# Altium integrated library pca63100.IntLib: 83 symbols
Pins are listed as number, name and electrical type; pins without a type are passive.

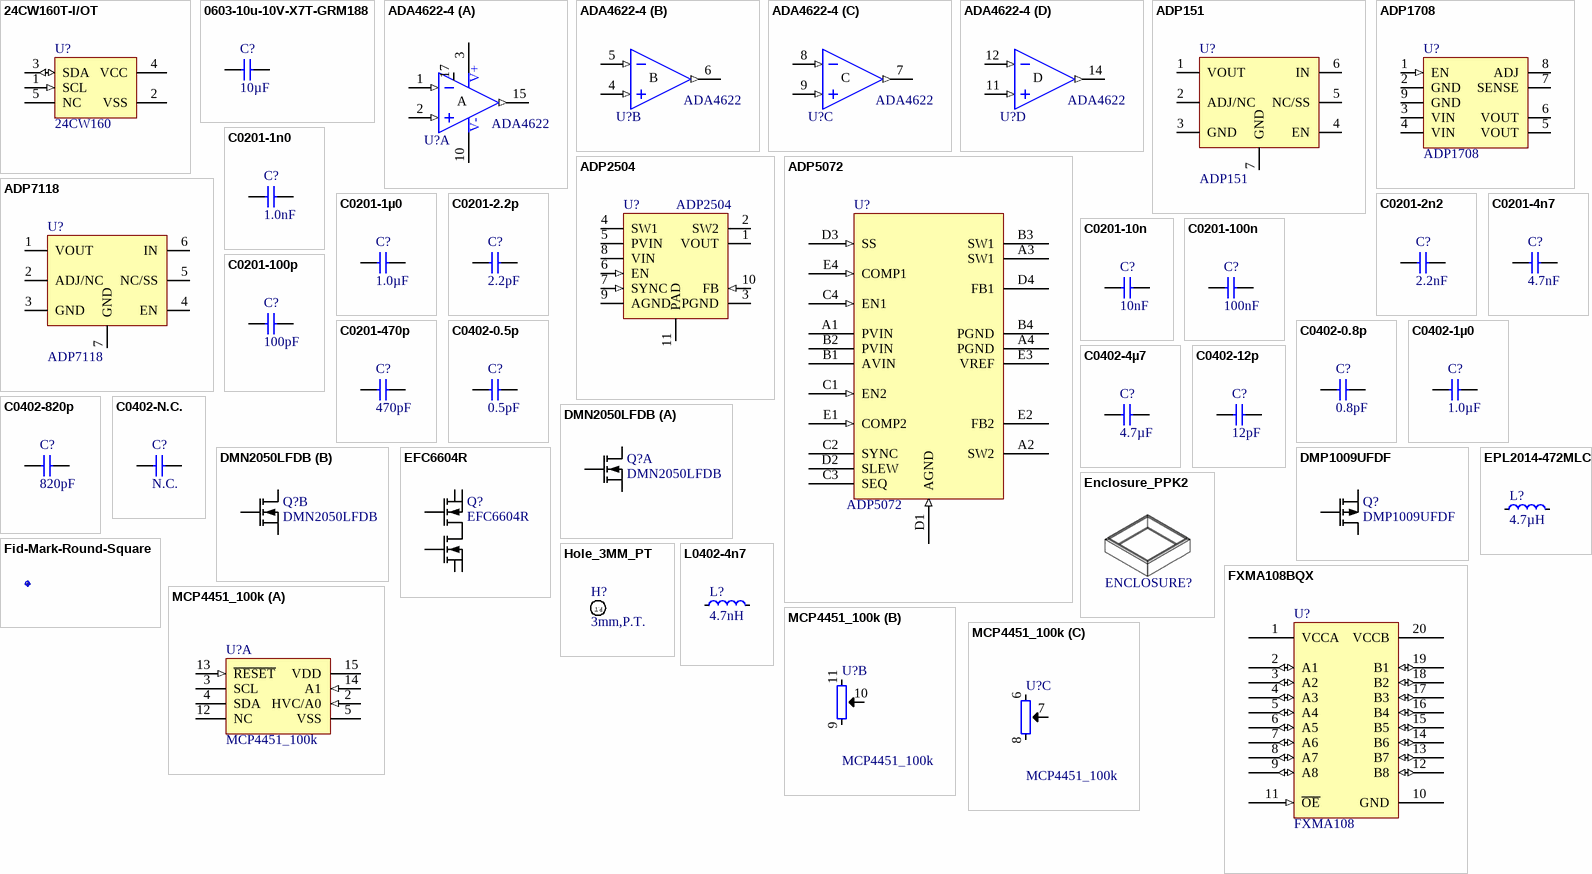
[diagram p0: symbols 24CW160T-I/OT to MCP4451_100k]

## 24CW160T-I/OT
designator U?, comment 24CW160
16 Kbit I2C Serial EEPROM with Software Write Protection, 1.6-5.5 V Supply; Part Number: 24CW160T-I/OT; Manufacturer: Microchip; Part number IPS: 00000004049; Artikkelnr Noca: N.A.; Pad Count: 5
footprint SOT-23-5
pins: 1 SCL (in), 2 VSS (power), 3 SDA (io), 4 VCC (power), 5 NC

## 0603-10u-10V-X7T-GRM188
designator C?, comment 10µF
CAP CER 10UF 10V X7T 0603; Part Number: 0603-10u-10V-X7T-GRM188; Manufacturer: Murata; Manufacturer Part Number: GRM188D71A106MA73; Part number IPS: 00000004696; Note: 10VDC; Artikkelnr Noca: N.A; Pad Count: 2
footprint CAPC1608X06L
pins: 1, 2

## ADA4622-4
designator U?, comment ADA4622
J-FET Amplifier 4 Circuit Rail-to-Rail 16-LFCSP (4x4); Part Number: ADA4622-4; Manufacturer: Analog Devices; Manufacturer Part Number: ADA4622-4ACPZ-RL; Part number IPS: 00000004963; Artikkelnr Noca: N.A.; Pad Count: 17
footprint QFN65P400X400X80_HS-17N
part A pins: 1 IN A- (in), 2 IN A+ (in), 3 VDD (power), 10 VSS (power), 13 NIC hidden, 15 OUTA (out), 16 NIC hidden, 17 EPAD (power) "Connect to VDD"
part B pins: 4 IN B+ (in), 5 IN B- (in), 6 OUTB (out)
part C pins: 7 OUTC (out), 8 IN C- (in), 9 IN C+ (in)
part D pins: 11 IN D+ (in), 12 IN D- (in), 14 OUTD (out)

## ADP151
designator U?
Ultralow Noise, 200 mA,CMOS Linear Regulator; Manufacturer: Analog Devices; Manufacturer Part Number: ADP151ACPZ-3.3-R7; Part number IPS: 00000004803; Artikkelnr Noca: N.A.; Pad Count: 7
footprint SON65P200X60_HS-7N
pins: 1 VOUT (power), 2 ADJ/NC, 3 GND, 4 EN, 5 NC/SS, 6 IN (power), 7 GND (power)

## ADP1708
designator U?
LDO, Adjustable, 1 Output 1A, 8-LFCSP-WD (3x3); Manufacturer: Analog Devices; Manufacturer Part Number: ADP1708ACPZ-R7; Part number IPS: 00000004966; Artikkelnr Noca: N.A.; Pad Count: 9
footprint SON50P300X80_HS-9N
pins: 1 EN (in), 2 GND (power), 3 VIN (power), 4 VIN (power), 5 VOUT (power), 6 VOUT (power), 7 SENSE, 8 ADJ, 9 GND (power)

## ADP2504
designator U?
Buck-Boost Switching Regulator IC Positive Adjustable 2.8V 1 Output 1A; Manufacturer: Analog Devices; Manufacturer Part Number: ADP2504ACPZ-R7; Part number IPS: 00000004965; Artikkelnr Noca: N.A.; Pad Count: 10
footprint SON50P300X80-HS-11N
pins: 1 VOUT (power), 2 SW2 (power), 3 PGND (power), 4 SW1 (power), 5 PVIN (power), 6 EN (in), 7 SYNC (in), 8 VIN (power), 9 AGND (power), 10 FB (in), 11 PAD (power)

## ADP5072
designator U?
Boost Switching Regulator IC Positive and Negative (Dual Rail) Adjustable 0.8V 2 Output 600mA, 1A 20-UFBGA,; Manufacturer: Analog Devices; Manufacturer Part Number: ADP5072ACBZ-R7; Part number IPS: 00000004804; Artikkelnr Noca: N.A.; Pad Count: 20
footprint BGA20C40P4X5_161X218X56
pins: A1 PVIN (power), A2 SW2 (power), A3 SW1 (power), A4 PGND (power), B1 AVIN (power), B2 PVIN (power), B3 SW1 (power), B4 PGND (power), C1 EN2 (in), C2 SYNC, C3 SEQ, C4 EN1 (in), D1 AGND (in), D2 SLEW, D3 SS (in), D4 FB1 (power), E1 COMP2 (in), E2 FB2 (power), E3 VREF (power), E4 COMP1 (in)

## ADP7118
designator U?
20 V, 200 mA, Low Noise,CMOS LDO Linear Regulator; Manufacturer: Analog Devices; Manufacturer Part Number: ADP7118ACPZN-R7; Part number IPS: 00000004964; Artikkelnr Noca: N.A.; Pad Count: 7
footprint SON65P200X60_HS-7N
pins: 1 VOUT (power), 2 ADJ/NC, 3 GND, 4 EN, 5 NC/SS, 6 IN (power), 7 GND (power)

## C0201-1n0
designator C?, comment 1.0nF
Capacitor, X7R, ±10%; Part Number: C0201-1n0; Part number IPS: 00000003206; Note: 16V; Artikkelnr Noca: N.A.; Pad Count: 2
footprint CAPC0603X03L_C
pins: 1, 2

## C0201-1µ0
designator C?, comment 1.0µF
Capacitor, X5R, ±10%; Part Number: C0201-1µ0; Part number IPS: 00000001723; Note: 10V; Artikkelnr Noca: N.A.; Pad Count: 2
footprint CAPC0603X03L_C
pins: 1, 2

## C0201-2.2p
designator C?, comment 2.2pF
Chip Cap 0201; Part Number: C0201-2.2p; Note: Chip Cap 1%; Artikkelnr Noca: N.A.; Pad Count: 2
footprint CAPC0603X03L_C
pins: 1, 2

## C0201-2n2
designator C?, comment 2.2nF
Capacitor, X7R, ±10%, 10V; Part Number: C0201-2n2; Part number IPS: 00000001778; Artikkelnr Noca: N.A.; Pad Count: 2
footprint CAPC0603X03L_C
pins: 1, 2

## C0201-4n7
designator C?, comment 4.7nF
Chip Cap 0201; Part Number: C0201-4n7; Part number IPS: 00000001243; Note: Chip Cap 1%; Artikkelnr Noca: N.A.; Pad Count: 2
footprint CAPC0603X03L_C
pins: 1, 2

## C0201-10n
designator C?, comment 10nF
Capacitor, X7R, ±10%; Part Number: C0201-10n; Part number IPS: 00000003480; Note: 10V; Artikkelnr Noca: N.A.; Pad Count: 2
footprint CAPC0603X03L_C
pins: 1, 2

## C0201-100n
designator C?, comment 100nF
Capacitor, X5R, ±10%; Part Number: C0201-100n; Part number IPS: 00000001248, 00000002505; Note: 16V; Artikkelnr Noca: N.A.; Pad Count: 2
footprint CAPC0603X03L_C
pins: 1, 2

## C0201-100p
designator C?, comment 100pF
Capacitor, NP0, ±2%, 25V; Part Number: C0201-100p; Manufacturer: Murata; Manufacturer Part Number: GRM0335C1E101GA01; Part number IPS: 00000007853; Artikkelnr Noca: N.A.; Pad Count: 2
footprint CAPC0603X03L_C
pins: 1, 2

## C0201-470p
designator C?, comment 470pF
Chip Cap 0201; Part Number: C0201-470p; Part number IPS: 00000005775; Note: Chip Cap 1%; Artikkelnr Noca: N.A.; Pad Count: 2
footprint CAPC0603X03L_C
pins: 1, 2

## C0402-0.5p
designator C?, comment 0.5pF
Capacitor, NP0, ±0.05pF; Part Number: C0402-0.5p; Manufacturer: Murata; Manufacturer Part Number: GJM1555C1HR50WB01; Part number IPS: 00000004293; Note: 50V; Artikkelnr Noca: 20020007; Pad Count: 2
footprint CAPC1005X04L
pins: 1, 2

## C0402-0.8p
designator C?, comment 0.8pF
Capacitor, NP0, ±5%; Part Number: C0402-0.8p; Manufacturer: Murata; Manufacturer Part Number: GRM1555C1HR80WA01D; Part number IPS: 00000007782; Note: 50V; Artikkelnr Noca: 20029147; Pad Count: 2
footprint CAPC1005X04L
pins: 1, 2

## C0402-1µ0
designator C?, comment 1.0µF
Capacitor, X5R, ±5%, 6.3V; Part Number: C0402-1µ0; Part number IPS: 00000007786, 00000003457; Artikkelnr Noca: 20039235; Pad Count: 2
footprint CAPC1005X04L
pins: 1, 2

## C0402-4µ7
designator C?, comment 4.7µF
Capacitor, X5R, ±20%; Part Number: C0402-4µ7; Part number IPS: 00000001251, 00000007165; Note: 10V; Artikkelnr Noca: 20039482; Pad Count: 2
footprint CAPC1005X04L
pins: 1, 2

## C0402-12p
designator C?, comment 12pF
Capacitor, NP0, ±2%; Part Number: C0402-12p; Part number IPS: 00000002398; Note: 50V; Artikkelnr Noca: 20029159; Pad Count: 2
footprint CAPC1005X04L
pins: 1, 2

## C0402-820p
designator C?, comment 820pF
Capacitor, NP0, ±5%; Part Number: C0402-820p; Part number IPS: 00000004365; Note: 50V; Artikkelnr Noca: 20029219; Pad Count: 2
footprint CAPC1005X04L
pins: 1, 2

## C0402-N.C.
designator C?, comment N.C.
Not mounted; Part Number: C0402-N.C.; Note: Chip Cap; Artikkelnr Noca: N.A.; Assembly: Not mounted; Pad Count: 2
footprint CAPC1005X04L_NC
pins: 1, 2

## DMN2050LFDB
designator Q?
Dual N Ch MOFET, 3.3A, 45mOhm @ 5A, 4.5V, 730mW; Manufacturer: Diodes Incorporated; Manufacturer Part Number: DMN2050LFDB-7; Part number IPS: 00000004782; Artikkelnr Noca: N.A.; Pad Count: 6
footprint DFN65P200X60_HS-6N
part A pins: 1 S1, 2 G1, 6 D1
part B pins: 3 D2, 4 S2, 5 G2

## DMP1009UFDF
designator Q?
P Ch MOFET, 11A, 30mOhm max, 2W; Manufacturer: Diodes Incorporated; Part number IPS: 00000004784; Artikkelnr Noca: N.A.; Pad Count: 6
footprint UDFN65P200X200X60_HS-6N
pins: 1 G, 2 S, 3 D

## EFC6604R
designator Q?
Dual MOSFET, Dual N Channel, 13 A, 12 V, 0.009 ohm, 4.5 V, 2.5 V; Manufacturer: ON Semiconductor; Manufacturer Part Number: EFC6604R-TR; Part number IPS: 00000004783; Artikkelnr Noca: N.A.; Pad Count: 6
footprint BGA6C65P2X3_146X191X22
pins: 1 S1, 2 G1, 3 S2, 4 S2, 5 G2, 6 S2

## Enclosure_PPK2
designator ENCLOSURE?, comment Plastic Enclosure  (value not drawn)
PPK2 Moulded plastic casing; Part Number: Enclosure_PPK2; Manufacturer: Proto Labs, Inc.; Manufacturer Part Number: PPK plexi rev 1.2; Part number IPS: 4971; Pad Count: 0
footprint Enclosure_PPK2

## EPL2014-472MLC
designator L?, comment 4.7µH
Shielded Power Inductor EPL2014 Low DCR Ind 4.7 uH 20 % 650mA; Part Number: EPL2014-472MLC; Manufacturer: Coilcraft; Part number IPS: 00000004697; Artikkelnr Noca: N.A.; Pad Count: 2
footprint IND_EPL2014
pins: 1, 2

## Fid-Mark-Round-Square
designator Fid?, comment Fiducial mark  (value not drawn)  (no BOM)
Part Number: Fid-Mark-Round-Square; Artikkelnr Noca: N.A.; Pad Count: 1
footprint Fiducial_Round-Square

## FXMA108BQX
designator U?, comment FXMA108
8-bit bidirectional voltage-level translator with auto-direction sensing; Part Number: FXMA108BQX; Manufacturer: Fairchild Semiconductor; Part number IPS: 00000004806; Note: Translator, Bidirectional; Artikkelnr Noca: N.A.; Pad Count: 20
footprint QFN50P450X250X80_HS-21N
pins: 1 VCCA (power), 2 A1 (io), 3 A2 (io), 4 A3 (io), 5 A4 (io), 6 A5 (io), 7 A6 (io), 8 A7 (io), 9 A8 (io), 10 GND (power), 11 ~{OE} (in), 12 B8 (io), 13 B7 (io), 14 B6 (io), 15 B5 (io), 16 B4 (io), 17 B3 (io), 18 B2 (io), 19 B1 (io), 20 VCCB (power)

## Hole_3MM_PT
designator H?, comment 3mm,P.T.  (no BOM)
Regular Plate Through, 3mm hole; Part Number: Hole_3MM_PT; Manufacturer: Nordic Semiconductor; Artikkelnr Noca: N.A.; Pad Count: 1
footprint HOLE_PT_3MM
pins: 1

## L0402-4n7
designator L?, comment 4.7nH
Inductor, 160mA, ±0.1nH; Part Number: L0402-4n7; Manufacturer: Murata; Manufacturer Part Number: LQP15MN4N7B02D; Part number IPS: 00000004366; Note: High frequency chip inductor ±5%; Artikkelnr Noca: 33029164; Pad Count: 2
footprint INDC1005X04L
pins: 1, 2

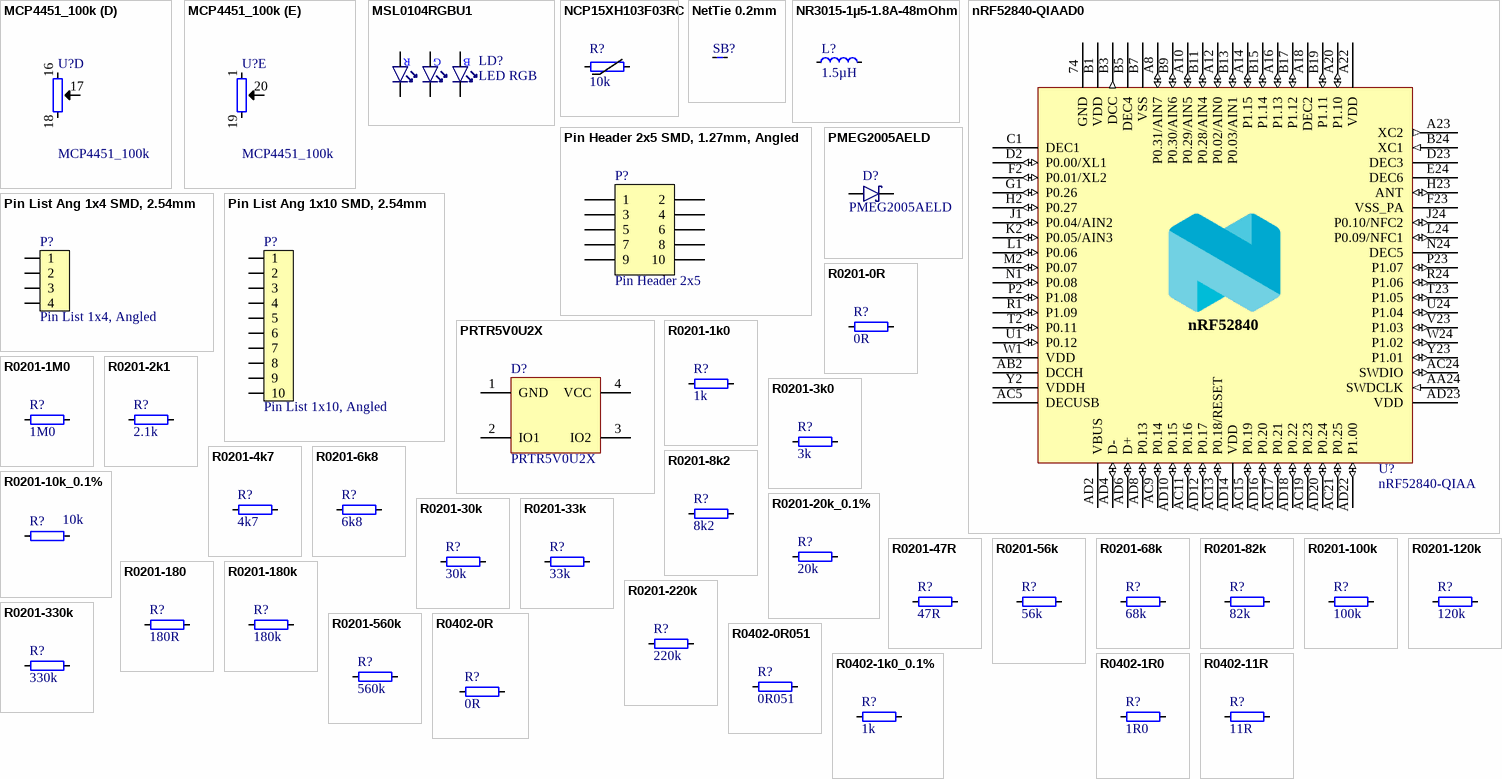
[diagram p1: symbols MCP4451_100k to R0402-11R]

## MCP4451_100k
designator U?
Quad Digital Potentiometer, 100k, 257 taps, I2C interface, Volatile Memory, 1.8-5.5V; Manufacturer: Microchip Technology; Manufacturer Part Number: MCP4451-104E/ML; Part number IPS: 00000004805; Artikkelnr Noca: 15070064; Pad Count: 20
footprint QFN50P400X400X80_HS-21N
part A pins: 2 HVC/A0 (in), 3 SCL, 4 SDA, 5 VSS (power), 12 NC, 13 ~{RESET} (in), 14 A1 (in), 15 VDD (power) "VDD 1.65V - 5.5V", 21 VSS (power) hidden to GND
part B pins: 9 P0A, 10 P0W (power), 11 P0B
part C pins: 6 P1B, 7 P1W (power), 8 P1A
part D pins: 16 P2B, 17 P2W (power), 18 P2A
part E pins: 1 P3B, 19 P3A, 20 P3W (power)

## MSL0104RGBU1
designator LD?, comment LED RGB
High brightness, side view RGB LED; Part Number: MSL0104RGBU1; Manufacturer: ROHM; Part number IPS: 00000007799; Artikkelnr Noca: N.A.; Pad Count: 7
footprint MSL0104
pins: 1 A_RED, 2 A_GREEN, 3 C_GREEN, 4 C_RED, 5 C_BLUE, 6 A_BLUE

## NCP15XH103F03RC
designator R?, comment 10k
THERMISTOR 10K OHM NTC 0402 SMD; Part Number: NCP15XH103F03RC; Manufacturer: Murata; Part number IPS: 00000007808; Note: Chip Res 1%; Artikkelnr Noca: N.A.; Pad Count: 2
footprint RESC1005X04L
pins: 1, 2

## NetTie 0.2mm
designator SB?, comment NetTie_200um  (value not drawn)  (net tie, no BOM)
Net Tie; Part Number: NetTie 0.2mm; Artikkelnr Noca: N.A.; Pad Count: 2
footprint NetTie_200um
pins: 1, 2

## NR3015-1µ5-1.8A-48mOhm
designator L?, comment 1.5µH
Ferrite Inductor, Shielded, 1,8A, 48mOhm; Part Number: NR3015-1µ5-1.8A-48mOhm; Manufacturer: Taiyo Yuden; Manufacturer Part Number: NR3015T1R5N; Part number IPS: 00000004698; Artikkelnr Noca: N.A.; Pad Count: 2
footprint TY-NR3015
pins: 1, 2

## nRF52840-QIAAD0
designator U?, comment nRF52840-QIAA
Multi-protocol Bluetooth Low Energy, IEEE 802.15.4, ANT and 2.4GHz proprietary system-on-chip; Part Number: nRF52840-QIAAD0; Manufacturer: Nordic Semiconductor; Part number IPS: 80000001648; Artikkelnr Noca: N.A.; Pad Count: 73
footprint AQFN50P700X700X85_HS-74N
pins: 74 GND (power), A8 P0.31/AIN7 (io), A10 P0.29/AIN5 (io), A12 P0.02/AIN0 (io), A14 P1.15 (io), A16 P1.13 (io), A18 DEC2 (power), A20 P1.10 (io), A22 VDD (power), A23 XC2 (out), AA24 SWDCLK (in), AB2 DCCH (power), AC5 DECUSB (power), AC9 P0.14 (io), AC11 P0.16 (io), AC13 P0.18/RESET (io), AC15 P0.19 (io), AC17 P0.21 (io), AC19 P0.23 (io), AC21 P0.25 (io), AC24 SWDIO (io), AD2 VBUS (power), AD4 D- (io), AD6 D+ (io), AD8 P0.13 (io), AD10 P0.15 (io), AD12 P0.17 (io), AD14 VDD (power), AD16 P0.20 (io), AD18 P0.22 (io), AD20 P0.24 (io), AD22 P1.00 (io), AD23 VDD (power), B1 VDD (power), B3 DCC (out), B5 DEC4 (power), B7 VSS (power), B9 P0.30/AIN6 (io), B11 P0.28/AIN4 (io), B13 P0.03/AIN1 (io), B15 P1.14 (io), B17 P1.12 (io), B19 P1.11 (io), B24 XC1 (in), C1 DEC1 (power), D2 P0.00/XL1 (io), D23 DEC3 (power), E24 DEC6 (power), F2 P0.01/XL2 (io), F23 VSS_PA (power), G1 P0.26 (io), H2 P0.27 (io), H23 ANT (io), J1 P0.04/AIN2 (io), J24 P0.10/NFC2 (io), K2 P0.05/AIN3 (io), L1 P0.06 (io), L24 P0.09/NFC1 (io), M2 P0.07 (io), N1 P0.08 (io), N24 DEC5 (power), P2 P1.08 (io), P23 P1.07 (io), R1 P1.09 (io), R24 P1.06 (io), T2 P0.11 (io), T23 P1.05 (io), U1 P0.12 (io), U24 P1.04 (io), V23 P1.03 (io), W1 VDD (power), W24 P1.02 (io), Y2 VDDH (power), Y23 P1.01 (io)

## Pin Header 2x5 SMD, 1.27mm, Angled
designator P?, comment Pin Header 2x5
Pin Header 2x5, 1.27mm (50mil); Part Number: Pin Header 2x5 SMD, 1.27mm, Angled; Manufacturer: W-CON; Manufacturer Part Number: 1325B-1205S0Z080CR02; Part number IPS: 00000007800; Artikkelnr Noca: N.A.; Pad Count: 10
footprint HDR_2x5-SMD-1.27mm-ANG
pins: 1, 2, 3, 4, 5, 6, 7, 8, 9, 10

## Pin List Ang 1x4 SMD, 2.54mm
designator P?, comment Pin List 1x4, Angled
Pin List 1x4, 2.54mm (100mil), Right Angled, SMD; Part Number: Pin List Ang 1x4 SMD, 2.54mm; Part number IPS: 00000004780; Artikkelnr Noca: N.A.; Pad Count: 4
footprint LIST_ANG_1x4-SMD-2.54MM
pins: 1, 2, 3, 4

## Pin List Ang 1x10 SMD, 2.54mm
designator P?, comment Pin List 1x10, Angled
Pin List 1x10, 2.54mm (100mil), Right Angled, SMD; Part Number: Pin List Ang 1x10 SMD, 2.54mm; Part number IPS: 00000004781; Artikkelnr Noca: N.A.; Pad Count: 10
footprint LIST_ANG_1x10-SMD-2.54MM
pins: 1, 2, 3, 4, 5, 6, 7, 8, 9, 10

## PMEG2005AELD
designator D?
DIODE SCHOTTKY 20V 0.5A DFN1006D-2/SOD882D; Manufacturer: NXP; Manufacturer Part Number: PMEG2005AELD, 315; Part number IPS: 00000004695; Artikkelnr Noca: N.A.; Pad Count: 2
footprint DFN1006D-2
pins: 1 C, 2 A

## PRTR5V0U2X
designator D?
Ultra low capacitance double rail-to-rail ESD protection diode; Manufacturer: NXP; Part number IPS: 00000009951; Artikkelnr Noca: 10069015; Pad Count: 4
footprint SOT190P230X110-4L
pins: 1 GND, 2 IO1, 3 IO2, 4 VCC

## R0201-0R
designator R?, comment 0R
Resistor, ±5%, 0.05W; Part Number: R0201-0R; Part number IPS: 00000003245; Note: Chip Res 5%; Artikkelnr Noca: N.A.; Pad Count: 2
footprint RESC0603X03L_C
pins: 1, 2

## R0201-1k0
designator R?, comment 1k
Resistor, ±1%, 0.05W; Part Number: R0201-1k0; Part number IPS: 00000005786; Note: Chip Res 1%; Artikkelnr Noca: N.A.; Pad Count: 2
footprint RESC0603X03L_C
pins: 1, 2

## R0201-1M0
designator R?, comment 1M0
Resistor, ±1%, 0.05W; Part Number: R0201-1M0; Part number IPS: 00000001418; Note: Chip Res 1%; Artikkelnr Noca: N.A.; Pad Count: 2
footprint RESC0603X03L_C
pins: 1, 2

## R0201-2k1
designator R?, comment 2.1k
RES SMD 2.1K OHM 1% 1/20W 0201; Part Number: R0201-2k1; Manufacturer: Panasonic; Manufacturer Part Number: ERJ-1GEF2101C; Part number IPS: 00000004787; Note: Chip Res 1%; Artikkelnr Noca: N.A.; Pad Count: 2
footprint RESC0603X03L_C
pins: 1, 2

## R0201-3k0
designator R?, comment 3k
Resistor, ±1%, 0.05W; Part Number: R0201-3k0; Part number IPS: 00000001688; Note: Chip Res 1%; Artikkelnr Noca: N.A.; Pad Count: 2
footprint RESC0603X03L_C
pins: 1, 2

## R0201-4k7
designator R?, comment 4k7
Resistor, ±1%, 0.05W; Part Number: R0201-4k7; Part number IPS: 00000001706; Note: Chip Res 1%; Artikkelnr Noca: N.A.; Pad Count: 2
footprint RESC0603X03L_C
pins: 1, 2

## R0201-6k8
designator R?, comment 6k8
Resistor, ±1%, 0.05W; Part Number: R0201-6k8; Part number IPS: 00000001705; Note: Chip Res 1%; Artikkelnr Noca: N.A.; Pad Count: 2
footprint RESC0603X03L_C
pins: 1, 2

## R0201-8k2
designator R?, comment 8k2
Resistor, ±1%, 0.05W; Part Number: R0201-8k2; Part number IPS: 00000004788; Note: Chip Res 1%; Artikkelnr Noca: N.A.; Pad Count: 2
footprint RESC0603X03L_C
pins: 1, 2

## R0201-10k_0.1%
designator R?, comment 10k
Resistor, ±0.1%, 0.031W; Part Number: R0201-10k_0.1%; Part number IPS: 00000004786; Note: Chip Res 0.1%; Artikkelnr Noca: N.A.; Pad Count: 2
footprint RESC0603X03L_C
pins: 1, 2

## R0201-20k_0.1%
designator R?, comment 20k
Resistor, ±0.1%, 0.031W; Part Number: R0201-20k_0.1%; Part number IPS: 00000004785; Note: Chip Res 0.1%; Artikkelnr Noca: N.A.; Pad Count: 2
footprint RESC0603X03L_C
pins: 1, 2

## R0201-30k
designator R?, comment 30k
Resistor, ±1%, 0.05W; Part Number: R0201-30k; Part number IPS: 00000004318; Note: Chip Res 1%; Artikkelnr Noca: N.A.; Pad Count: 2
footprint RESC0603X03L_C
pins: 1, 2

## R0201-33k
designator R?, comment 33k
Resistor, ±1%, 0.05W; Part Number: R0201-33k; Part number IPS: 00000001708; Note: Chip Res 1%; Artikkelnr Noca: N.A.; Pad Count: 2
footprint RESC0603X03L_C
pins: 1, 2

## R0201-47R
designator R?, comment 47R
Resistor, ±1%, 0.05W; Part Number: R0201-47R; Part number IPS: 00000004794; Note: Chip Res 1%; Artikkelnr Noca: N.A.; Pad Count: 2
footprint RESC0603X03L_C
pins: 1, 2

## R0201-56k
designator R?, comment 56k
Resistor, ±1%, 0.05W; Part Number: R0201-56k; Part number IPS: 00000007882; Note: Chip Res 1%; Artikkelnr Noca: N.A.; Pad Count: 2
footprint RESC0603X03L_C
pins: 1, 2

## R0201-68k
designator R?, comment 68k
Resistor, ±1%, 0.05W; Part Number: R0201-68k; Part number IPS: 00000004800; Note: Chip Res 1%; Artikkelnr Noca: N.A.; Pad Count: 2
footprint RESC0603X03L_C
pins: 1, 2

## R0201-82k
designator R?, comment 82k
Resistor, ±1%, 0.05W; Part Number: R0201-82k; Part number IPS: 00000004801; Note: Chip Res 1%; Artikkelnr Noca: N.A.; Pad Count: 2
footprint RESC0603X03L_C
pins: 1, 2

## R0201-100k
designator R?, comment 100k
Resistor, ±1%, 0.05W; Part Number: R0201-100k; Part number IPS: 00000001419; Note: Chip Res 1%; Artikkelnr Noca: N.A.; Pad Count: 2
footprint RESC0603X03L_C
pins: 1, 2

## R0201-120k
designator R?, comment 120k
Resistor, ±1%, 0.05W; Part Number: R0201-120k; Part number IPS: 00000001425; Note: Chip Res 1%; Artikkelnr Noca: N.A.; Pad Count: 2
footprint RESC0603X03L_C
pins: 1, 2

## R0201-180
designator R?, comment 180R
Resistor, ±1%, 0.05W; Part Number: R0201-180; Part number IPS: 00000005783; Note: Chip Res 1%; Artikkelnr Noca: N.A.; Pad Count: 2
footprint RESC0603X03L_C
pins: 1, 2

## R0201-180k
designator R?, comment 180k
Resistor, ±1%, 0.05W; Part Number: R0201-180k; Part number IPS: 00000004797; Note: Chip Res 1%; Artikkelnr Noca: N.A.; Pad Count: 2
footprint RESC0603X03L_C
pins: 1, 2

## R0201-220k
designator R?, comment 220k
Resistor, ±1%, 0.05W; Part Number: R0201-220k; Part number IPS: 00000004789; Note: Chip Res 1%; Artikkelnr Noca: N.A.; Pad Count: 2
footprint RESC0603X03L_C
pins: 1, 2

## R0201-330k
designator R?, comment 330k
Resistor, ±1%, 0.05W; Part Number: R0201-330k; Part number IPS: 00000001424; Note: Chip Res 1%; Artikkelnr Noca: N.A.; Pad Count: 2
footprint RESC0603X03L_C
pins: 1, 2

## R0201-560k
designator R?, comment 560k
Resistor, ±1%, 0.05W; Part Number: R0201-560k; Part number IPS: 00000004799; Note: Chip Res 1%; Artikkelnr Noca: N.A.; Pad Count: 2
footprint RESC0603X03L_C
pins: 1, 2

## R0402-0R
designator R?, comment 0R
Resistor, ±5%, 0.063W; Part Number: R0402-0R; Part number IPS: 00000007128; Note: Chip Res 5%; Artikkelnr Noca: 27049000; Pad Count: 2
footprint RESC1005X04L
pins: 1, 2

## R0402-0R051
designator R?, comment 0R051
RES SMD 0.051 OHM 1% 1/4W 0402; Part Number: R0402-0R051; Manufacturer: Panasonic; Manufacturer Part Number: ERJ-2BWFR051X; Part number IPS: 00000004796; Note: Chip Res 1%; Artikkelnr Noca: N.A.; Pad Count: 2
footprint RESC1005X04L
pins: 1, 2

## R0402-1k0_0.1%
designator R?, comment 1k
Resistor, ±0.1%, 0.063W; Part Number: R0402-1k0_0.1%; Part number IPS: 00000004790; Note: Chip Res 0.1%; Artikkelnr Noca: 27469397; Pad Count: 2
footprint RESC1005X04L
pins: 1, 2

## R0402-1R0
designator R?, comment 1R0
Resistor, ±1%, 0.063W; Part Number: R0402-1R0; Part number IPS: 00000004795; Note: Chip Res 1%; Artikkelnr Noca: 27049001; Pad Count: 2
footprint RESC1005X04L
pins: 1, 2

## R0402-11R
designator R?, comment 11R
Resistor, ±1%, 0.063W; Part Number: R0402-11R; Part number IPS: 00000007807; Note: Chip Res 1%; Artikkelnr Noca: N.A.; Pad Count: 2
footprint RESC1005X04L
pins: 1, 2

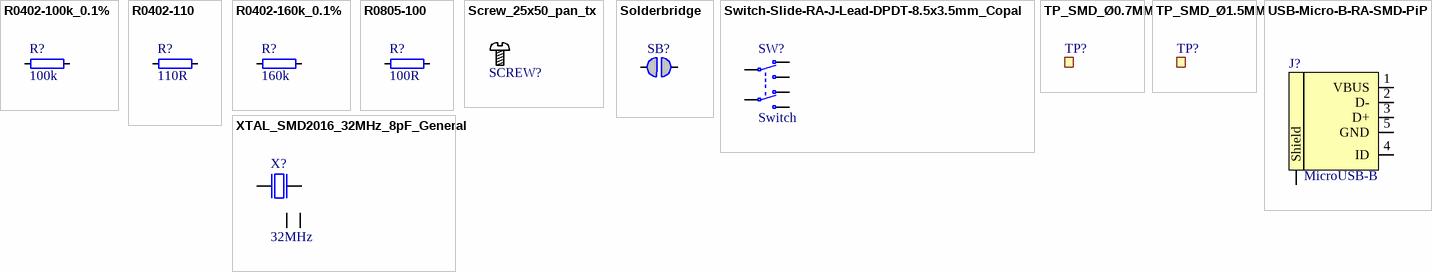
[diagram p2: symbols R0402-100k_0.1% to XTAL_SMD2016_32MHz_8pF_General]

## R0402-100k_0.1%
designator R?, comment 100k
Resistor, ±0.1%, 0.063W; Part Number: R0402-100k_0.1%; Part number IPS: 00000004792; Note: Chip Res 1%; Artikkelnr Noca: N.A.; Pad Count: 2
footprint RESC1005X04L
pins: 1, 2

## R0402-110
designator R?, comment 110R
Resistor, ±1%, 0.063W; Part Number: R0402-110; Part number IPS: 00000004793; Note: Chip Res 1%; Artikkelnr Noca: N.A.; Pad Count: 2
footprint RESC1005X04L
pins: 1, 2

## R0402-160k_0.1%
designator R?, comment 160k
Resistor, ±0.1%, 0.063W; Part Number: R0402-160k_0.1%; Part number IPS: 00000004798; Note: Chip Res 0.1%; Artikkelnr Noca: N.A.; Pad Count: 2
footprint RESC1005X04L
pins: 1, 2

## R0805-100
designator R?, comment 100R
Resistor, ±1%, 0.125W; Part Number: R0805-100; Part number IPS: 00000004791; Note: Chip Res 1%; Artikkelnr Noca: 27089049; Pad Count: 2
footprint RESC2012X11L
pins: 1, 2

## Screw_25x50_pan_tx
designator SCREW?, comment Screw  (value not drawn)
Pan head, torx, 2.5x5mm screw; Part Number: Screw_25x50_pan_tx; Manufacturer: Bossard; Manufacturer Part Number: 3205129; Part number IPS: 4972; Pad Count: 0
footprint Screw_25x50_pan_tx

## Solderbridge
designator SB?  (value not drawn)  (no BOM)
Artikkelnr Noca: N.A.; Pad Count: 2
footprint Solderbridge
pins: 1 0, 2 1

## Switch-Slide-RA-J-Lead-DPDT-8.5x3.5mm_Copal
designator SW?, comment Switch
SMD slide Switch (ON-ON); Part Number: Switch-Slide-RA-J-Lead-DPDT-8.5x3.5mm_Copal; Manufacturer: Copal Electronics Inc; Manufacturer Part Number: CL-SB-22A-11T; Part number IPS: 00000007811; Artikkelnr Noca: N.A.; Pad Count: 6
footprint Switch-Slide-RA-J-Lead-DPDT-8.5x3.5mm
pins: 1 N.O-1, 2 COM-1, 3 N.C-1, 4 N.O-2, 5 COM-2, 6 N.C-2

## TP_SMD_Ø0.7MM
designator TP?, comment Ø0.7mm,SMD  (value not drawn)  (no BOM)
0.7mm circular SMD testpad; Part Number: TP_SMD_Ø0.7MM; Manufacturer: Nordic Semiconductor; Artikkelnr Noca: N.A.; Pad Count: 1
footprint TP_SMD_Ø0.7mm
pins: 1

## TP_SMD_Ø1.5MM
designator TP?, comment Ø1.5mm,SMD  (value not drawn)  (no BOM)
1.5mm circular SMD testpad; Part Number: TP_SMD_Ø1.5MM; Manufacturer: Nordic Semiconductor; Artikkelnr Noca: N.A.; Pad Count: 1
footprint TP_SMD_Ø1.5mm
pins: 1

## USB-Micro-B-RA-SMD-PiP
designator J?, comment MicroUSB-B
MicroUSB-B-SMT; Part Number: USB-Micro-B-RA-SMD-PiP; Manufacturer: Allen Creations Corp.; Manufacturer Part Number: AJU55-BS2111-L; 2nd source part number: 609-4616-1-ND; Part number IPS: 00000007790; Artikkelnr Noca: 55029020; Artikkelnr Simpro: N.A.; Pad Count: 5
footprint USB-Micro-B-RA-SMD-PiP
pins: 1 VBUS (power), 2 D-, 3 D+, 4 ID, 5 GND (power), 6 Shield (power)

## XTAL_SMD2016_32MHz_8pF_General
designator X?, comment 32MHz
XTAL SMD 2016, 32MHz, Cl=8pF, Total Tol: ±40ppm; Part Number: XTAL_SMD2016_32MHz_8pF_General; Part number IPS: 00000007827; Note: XTAL SMD 32.000MHz; Artikkelnr Noca: N.A.; Pad Count: 4
footprint BT-XTAL_2016
pins: 1 inp, 2 GND, 3 out, 4 GND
